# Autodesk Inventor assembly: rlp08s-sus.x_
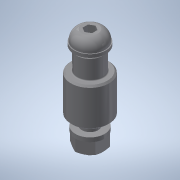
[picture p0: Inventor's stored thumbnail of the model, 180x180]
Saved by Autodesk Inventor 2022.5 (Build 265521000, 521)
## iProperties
Part Number: rlp08s-sus.x_
Material: 一般
Document SubType Name: Assembly
Designer: ImaoCorp
Sending System: SOLIDWORKS 2017-2017317
MC: AMD64
MC_MODEL: Intel64 Family 6 Model 60 Stepping 3, GenuineIntel
OS: Windows_NT
FRU: Parasolid Version 29.0, build 201,  4-17-2017
FORMAT: text
GUISE: transmit
KEY: rlp08s-sus
FILE: rlp08s-sus.x_t
DATE: Wed Sep 04 15:58:37 2019
Author: ImaoCorp
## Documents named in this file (3)
- X:\14_SW2022-Inv2022\00_全2023-1023新製品(TCC)まで\r\rlp08s-sus\RLP08S-SUS.iam
- X:\14_SW2022-Inv2022\00_全2023-1023新製品(TCC)まで\r\rlp08s-sus\rlp08s-sus_01.ipt
- X:\14_SW2022-Inv2022\00_全2023-1023新製品(TCC)まで\r\rlp08s-sus\rlp08s-sus_02.ipt
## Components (2 placed, 2 different names)
1. rlp08s-sus_01
2. rlp08s-sus_02
